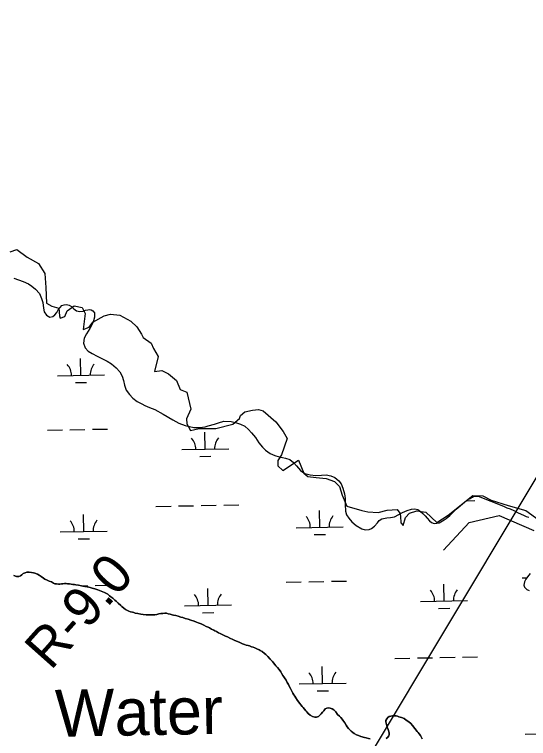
# Model space of a CAD drawing. Extents: x 3925854 to 3964121, y 224593 to 250589.
# Drawn here: x 3947714 to 3948807, y 239589 to 241130 of the extents above; entities that cross this region are included whole.
import ezdxf

# ---------------------------------------------------------------- set-up
doc = ezdxf.new("R2010")
doc.units = 0
for name, color, linetype in [('V-RIVR-EDGE', 7, 'Continuous'), ('V-RIVR-IDEN', 7, 'Continuous'), ('V-RIVR-RANG-IDEN', 7, 'Continuous'), ('V-RRAP-FSHR', 7, 'Continuous'), ('V-TOPO-SHOR', 7, 'Continuous'), ('V-UTIL-LINE', 7, 'Continuous'), ('V-WETL-SWMP', 7, 'Continuous')]:
    doc.layers.add(name, color=color, linetype=linetype)

msp = doc.modelspace()

# ---------------------------------------------------------------- linework, layer by layer
at = {"layer": 'V-RIVR-EDGE'}
msp.add_lwpolyline([(3947704.798, 240625.245), (3947719.549, 240630.163), (3947740.858, 240613.772), (3947765.444, 240600.659), (3947778.557, 240579.351), (3947781.015, 240549.028), (3947782.654, 240516.246), (3947793.309, 240509.689), (3947808.88, 240505.592), (3947809.699, 240489.201), (3947811.339, 240484.284), (3947821.173, 240487.562), (3947826.09, 240499.855), (3947840.842, 240510.509), (3947858.053, 240506.411), (3947864.609, 240494.118), (3947860.511, 240459.697), (3947872.805, 240464.614), (3947881, 240475.269), (3947904.767, 240489.201), (3947918.699, 240492.479), (3947938.368, 240490.02), (3947961.315, 240477.727), (3947974.428, 240465.434), (3947984.263, 240449.863), (3947987.541, 240442.487), (3948004.751, 240431.013), (3948009.669, 240419.539), (3948019.503, 240402.329), (3948012.127, 240370.367), (3948027.699, 240372.825), (3948041.631, 240365.449), (3948058.841, 240351.517), (3948066.217, 240331.848), (3948080.969, 240326.111), (3948089.165, 240290.051), (3948080.15, 240269.563), (3948080.969, 240258.908), (3948088.345, 240244.976), (3948107.195, 240249.074), (3948142.435, 240249.074), (3948178.495, 240258.089), (3948192.427, 240270.382), (3948194.886, 240276.938), (3948203.901, 240284.314), (3948220.292, 240288.412), (3948233.405, 240289.232), (3948243.239, 240286.773), (3948270.284, 240263.006), (3948285.856, 240242.518), (3948294.051, 240227.766), (3948281.758, 240193.345), (3948274.382, 240181.052), (3948274.382, 240169.578), (3948285.036, 240159.743), (3948317.818, 240181.871), (3948329.292, 240154.007), (3948338.307, 240146.631), (3948355.517, 240144.992), (3948376.825, 240142.533), (3948394.855, 240135.977), (3948405.509, 240125.323), (3948411.246, 240107.293), (3948421.081, 240083.526), (3948453.043, 240074.511), (3948465.336, 240072.052), (3948487.464, 240070.413), (3948506.313, 240075.33), (3948527.622, 240076.969), (3948533.358, 240068.774), (3948534.998, 240062.217), (3948535.817, 240048.285), (3948540.734, 240042.548), (3948545.652, 240059.759), (3948553.847, 240068.774), (3948569.418, 240073.691), (3948589.088, 240071.232), (3948612.035, 240049.105), (3948636.621, 240064.676), (3948689.072, 240106.473), (3948710.38, 240105.653), (3948727.591, 240096.638), (3948763.651, 240085.165), (3948801.35, 240074.511), (3948830.034, 240054.022)], dxfattribs=at)
at = {"layer": 'V-RRAP-FSHR'}
msp.add_lwpolyline([(3948626.157, 239990.445), (3948680.818, 240048.86), (3948744.685, 240063.583), (3948818.268, 240032.187)], dxfattribs=at)
at = {"layer": 'V-TOPO-SHOR'}
for points in [[(3947712.714, 239935.894), (3947718.647, 239934.219), (3947723.284, 239933.969), (3947726.829, 239935.243), (3947729.574, 239937.334), (3947733.035, 239940.322), (3947736.987, 239942.198), (3947740.731, 239943.269), (3947745.474, 239943.521), (3947750.41, 239942.866), (3947754.635, 239941.815), (3947757.654, 239941.076), (3947763.38, 239938.899), (3947766.585, 239936.746), (3947770.992, 239933.877), (3947775.598, 239930.502), (3947778.807, 239928.653), (3947784.028, 239926.379), (3947788.042, 239924.421), (3947793.168, 239922.654), (3947797.272, 239919.586), (3947800.289, 239918.746), (3947803.613, 239918.208), (3947807.641, 239917.661), (3947810.871, 239917.931), (3947814.002, 239918.302), (3947817.132, 239918.572), (3947820.564, 239918.838), (3947823.892, 239918.904), (3947827.32, 239918.669), (3947831.148, 239918.324), (3947835.076, 239917.78), (3947838.498, 239917.038), (3947841.622, 239916.704), (3947844.745, 239916.268), (3947850.684, 239915.297), (3947856.525, 239914.228), (3947859.847, 239913.69), (3947864.176, 239912.84), (3947869.008, 239911.881), (3947872.026, 239911.142), (3947875.045, 239910.507), (3947879.37, 239909.352), (3947885.406, 239907.777), (3947891.335, 239905.699), (3947895.154, 239904.347), (3947902.185, 239901.551), (3947905.296, 239900.107), (3947909.611, 239897.945), (3947912.519, 239896.2), (3947916.521, 239893.132), (3947919.323, 239890.883), (3947923.226, 239887.918), (3947927.523, 239884.041), (3947930.318, 239881.288), (3947934.713, 239877.106), (3947940.311, 239872.308), (3947942.711, 239870.266), (3947946.61, 239866.897), (3947950.209, 239863.833), (3947953.016, 239862.291), (3947957.235, 239860.534), (3947961.155, 239859.18), (3947964.977, 239858.031), (3947968.194, 239857.091), (3947971.111, 239856.254), (3947976.847, 239854.984), (3947982.784, 239853.712), (3947988.021, 239852.952), (3947994.47, 239852.381), (3948000.524, 239852.418), (3948006.271, 239852.258), (3948012.429, 239852.698), (3948017.074, 239853.356), (3948021.321, 239854.32)], [(3948021.321, 239854.32), (3948025.462, 239854.984), (3948029.706, 239855.645), (3948033.642, 239855.908), (3948037.271, 239855.668), (3948040.691, 239854.826), (3948044.918, 239853.974), (3948049.547, 239852.817), (3948052.566, 239852.08), (3948057.495, 239850.818), (3948062.12, 239849.46), (3948067.852, 239847.785), (3948071.975, 239846.534), (3948077.103, 239844.967), (3948083.64, 239843.185), (3948089.37, 239841.309), (3948096.102, 239838.919), (3948101.128, 239837.154), (3948104.945, 239835.702), (3948110.971, 239833.117), (3948116.793, 239830.435), (3948122.013, 239827.958), (3948126.13, 239826.101), (3948129.04, 239824.659), (3948133.351, 239822.294), (3948137.767, 239820.029), (3948140.574, 239818.486), (3948143.581, 239816.641), (3948148.197, 239814.274), (3948151.308, 239812.728), (3948155.521, 239810.567), (3948160.039, 239808.502), (3948162.949, 239807.059), (3948166.965, 239805.304), (3948171.882, 239802.832), (3948178.507, 239799.735), (3948181.62, 239798.494), (3948186.644, 239796.626), (3948191.867, 239794.453), (3948194.779, 239793.212), (3948198.789, 239790.75), (3948203.614, 239789.188), (3948206.831, 239788.248), (3948211.054, 239786.992), (3948213.971, 239786.155), (3948218.091, 239784.701), (3948221.608, 239783.353), (3948225.425, 239782.001), (3948229.644, 239780.242), (3948234.164, 239778.28), (3948236.871, 239776.84), (3948240.982, 239774.377), (3948245.883, 239770.391), (3948248.58, 239767.841), (3948252.973, 239763.561), (3948257.861, 239758.365), (3948262.748, 239752.969), (3948264.74, 239750.528), (3948267.827, 239746.763), (3948270.02, 239744.22), (3948273.61, 239740.249), (3948276.695, 239736.181), (3948280.471, 239730.797), (3948282.257, 239727.955), (3948285.036, 239723.588), (3948286.822, 239720.746), (3948289.802, 239716.277), (3948291.788, 239713.23), (3948294.365, 239708.765), (3948296.835, 239703.899), (3948298.416, 239700.655), (3948300.783, 239695.586), (3948302.962, 239691.629), (3948306.229, 239685.745), (3948308.31, 239682.194), (3948310.196, 239679.149), (3948312.578, 239675.493), (3948316.352, 239669.906), (3948321.132, 239663.905), (3948323.02, 239661.161), (3948325.906, 239657.501), (3948327.901, 239655.161), (3948330.788, 239651.701), (3948333.983, 239648.441), (3948335.974, 239646), (3948338.964, 239642.539), (3948343.062, 239638.764), (3948347.676, 239636.296), (3948352.501, 239634.734), (3948356.436, 239634.793), (3948360.384, 239636.266), (3948363.333, 239638.656), (3948366.289, 239641.55), (3948369.35, 239644.947), (3948372.009, 239648.449), (3948374.972, 239652.05), (3948378.318, 239653.831), (3948381.956, 239654.296), (3948385.476, 239653.555), (3948389.499, 239652.304), (3948393.111, 239650.45)], [(3948393.111, 239650.45), (3948397.703, 239645.863), (3948401.275, 239640.077), (3948405.274, 239636.808), (3948408.068, 239633.853), (3948410.859, 239630.697), (3948412.649, 239628.158), (3948414.437, 239625.518), (3948416.319, 239622.27), (3948419.297, 239617.598), (3948421.578, 239613.842), (3948424.165, 239610.287), (3948426.958, 239607.534), (3948429.959, 239604.98), (3948433.457, 239601.919), (3948436.16, 239599.875), (3948441.778, 239596.891), (3948445.595, 239595.439), (3948450.92, 239593.569), (3948458.666, 239591.369), (3948462.188, 239590.626), (3948466.915, 239589.366), (3948470.737, 239588.32)], [(3948504.735, 239588.975), (3948507.682, 239591.062), (3948510.441, 239594.564), (3948511.18, 239597.683), (3948510.916, 239601.519), (3948508.77, 239608.401), (3948506.806, 239613.564), (3948505.151, 239619.331), (3948503.892, 239624.387), (3948504.025, 239627.513), (3948505.677, 239631.125), (3948508.127, 239633.824), (3948511.07, 239635.711), (3948514.105, 239636.587), (3948517.945, 239637.253), (3948521.277, 239637.724), (3948525.51, 239637.275), (3948528.629, 239636.536), (3948531.746, 239635.696), (3948537.274, 239633.824), (3948542.498, 239631.754), (3948547.307, 239628.575), (3948552.614, 239624.789), (3948556.707, 239620.814), (3948560.699, 239616.636), (3948570.658, 239604.327), (3948572.651, 239601.988), (3948574.84, 239599.039), (3948577.523, 239595.279), (3948579.7, 239591.222), (3948581.085, 239588.385)]]:
    msp.add_lwpolyline(points, dxfattribs=at)
at = {"layer": 'V-UTIL-LINE'}
msp.add_lwpolyline([(3951084.343, 243921.319), (3947981.77, 238738.296), (3948844.302, 237642.921), (3949260.796, 236134.673), (3945931.135, 235655.081), (3945509.058, 234777.685), (3942603.575, 230254.808)], dxfattribs=at)
at = {"layer": 'V-WETL-SWMP'}
for p, q in [((3947855.392, 240362.345), (3947854.738, 240398.339)), ((3947805.401, 240361.436), (3947905.384, 240363.254)), ((3947843.675, 240346.699), (3947867.671, 240347.135)), ((3947784.095, 240245.598), (3947816.09, 240246.179)), ((3947832.087, 240246.47), (3947864.082, 240247.052)), ((3947880.079, 240247.343), (3947912.074, 240247.925)), ((3948119.728, 240205.263), (3948119.073, 240241.257)), ((3948069.736, 240204.354), (3948169.72, 240206.172)), ((3948108.01, 240189.616), (3948132.006, 240190.053)), ((3948674.753, 240095.264), (3948692.88, 240095.594)), ((3948015.084, 240083.269), (3948047.079, 240083.851)), ((3948063.076, 240084.142), (3948095.071, 240084.724)), ((3948111.068, 240085.015), (3948143.063, 240085.596)), ((3948159.061, 240085.887), (3948191.055, 240086.469)), ((3947861.44, 240029.725), (3947860.786, 240065.719)), ((3948363.265, 240038.85), (3948362.611, 240074.844)), ((3947811.449, 240028.816), (3947911.432, 240030.634)), ((3948313.274, 240037.941), (3948413.257, 240039.759)), ((3947849.723, 240014.079), (3947873.719, 240014.515)), ((3948351.548, 240023.203), (3948375.544, 240023.64)), ((3948291.968, 239922.102), (3948323.963, 239922.684)), ((3948339.96, 239922.975), (3948371.955, 239923.557)), ((3948387.952, 239923.848), (3948419.947, 239924.429)), ((3948793.793, 239931.227), (3948803.644, 239931.406)), ((3947856.77, 239914.189), (3947870.13, 239914.432)), ((3947886.127, 239914.723), (3947918.122, 239915.305)), ((3948125.776, 239872.643), (3948125.121, 239908.637)), ((3948627.601, 239881.768), (3948626.946, 239917.762)), ((3948577.609, 239880.859), (3948677.593, 239882.677)), ((3948075.784, 239871.734), (3948175.768, 239873.552)), ((3948615.883, 239866.121), (3948639.879, 239866.557)), ((3948114.058, 239856.996), (3948138.054, 239857.433)), ((3948522.957, 239759.774), (3948554.952, 239760.356)), ((3948570.95, 239760.647), (3948602.944, 239761.228)), ((3948618.942, 239761.519), (3948650.936, 239762.101)), ((3948666.934, 239762.392), (3948698.928, 239762.974)), ((3948369.313, 239706.23), (3948368.659, 239742.224)), ((3948319.322, 239705.321), (3948419.305, 239707.139)), ((3948357.596, 239690.583), (3948381.592, 239691.02)), ((3948799.841, 239598.607), (3948831.836, 239599.189))]:
    msp.add_line(p, q, dxfattribs=at)
for points in [[(3947713.091, 240569.298), (3947722.635, 240565.568), (3947732.883, 240561.73), (3947743.928, 240556.875), (3947750.938, 240552.062), (3947758.641, 240545.93), (3947767.318, 240536.459), (3947771.851, 240526.124), (3947774.179, 240517.224), (3947775.773, 240505.608), (3947777.306, 240497.725), (3947781.971, 240490.515), (3947789.695, 240486.4), (3947795.863, 240487.849), (3947800.335, 240491.131), (3947804.218, 240495.933), (3947807.406, 240501.85), (3947811.09, 240506.956), (3947814.759, 240510.65), (3947819.721, 240512.515), (3947824.769, 240512.967), (3947830.203, 240511.7), (3947835.317, 240508.823), (3947840.614, 240504.128), (3947846.218, 240499.834), (3947852.956, 240497.949), (3947859.926, 240498.885), (3947865.392, 240500.745), (3947869.942, 240501.908), (3947874.384, 240502.265), (3947877.404, 240501.629), (3947881.015, 240499.776), (3947884.399, 240495.403), (3947884.204, 240486.328), (3947882.509, 240478.478), (3947879.712, 240471.345), (3947874.673, 240462.017), (3947867.598, 240450.895), (3947862.654, 240441.061), (3947860.733, 240430.894)], [(3947860.733, 240430.894), (3947864.761, 240420.564), (3947871.047, 240413.943), (3947879.161, 240408.513), (3947889.996, 240402.853), (3947900.132, 240397.906), (3947911.268, 240392.142), (3947920.39, 240386.702), (3947930.793, 240378.323), (3947938.066, 240369.674), (3947942.915, 240360.647), (3947946.042, 240350.931), (3947948.16, 240341.226), (3947951.784, 240330.8), (3947958.543, 240321.147), (3947965.927, 240313.506), (3947975.434, 240306.246), (3947984.664, 240301.41), (3947991.386, 240298.011), (3948001.228, 240293.875), (3948012.378, 240289.422), (3948030.232, 240279.856), (3948051.182, 240267.233), (3948064.019, 240260.14), (3948077.182, 240255.263), (3948095.7, 240251.339), (3948108.507, 240251.004), (3948119.519, 240252.806), (3948126.294, 240254.451), (3948139.346, 240258.35), (3948147.744, 240260.885), (3948159.279, 240264.397), (3948175.313, 240264.028), (3948185.977, 240261.396), (3948194.823, 240258.48), (3948203.955, 240253.947), (3948212.152, 240246.802), (3948218.436, 240240.08), (3948226.599, 240229.606), (3948233.851, 240218.94), (3948241.319, 240209.583), (3948248.005, 240202.655), (3948257.618, 240195.898), (3948267.562, 240191.962), (3948277.115, 240189.14), (3948284.257, 240187.25), (3948290.395, 240185.774), (3948299.745, 240182.853), (3948307.346, 240176.621), (3948313.727, 240169.495), (3948317.814, 240164.813), (3948322.7, 240159.416), (3948331.714, 240153.271), (3948342.677, 240150.232), (3948354.772, 240149.4), (3948366.782, 240150.083), (3948376.672, 240150.585), (3948386.537, 240148.667), (3948395.073, 240145.049), (3948403.671, 240137.697), (3948408.648, 240131.291), (3948412.383, 240121.872), (3948415.79, 240110.035), (3948417.605, 240100.233), (3948417.57, 240087.121), (3948417.831, 240073.401), (3948420.367, 240065.103), (3948424.933, 240057.995), (3948431.616, 240050.765), (3948440.912, 240042.599), (3948452.54, 240035.62), (3948459.781, 240033.628), (3948468.061, 240034.45), (3948473.426, 240036.311), (3948479.731, 240041.289), (3948485.757, 240048.488), (3948489.841, 240053.288), (3948495.426, 240056.861), (3948506.042, 240059.272), (3948514.012, 240059.492), (3948522.096, 240060.921), (3948531.729, 240065.764), (3948539.341, 240070.324), (3948548.865, 240074.462), (3948558.072, 240077.191), (3948565.14, 240077.924), (3948571.983, 240076.441), (3948577.794, 240072.649), (3948582.187, 240068.266), (3948587.376, 240062.867), (3948591.563, 240058.183), (3948596.449, 240052.686), (3948601.148, 240048.704), (3948606.478, 240047.135), (3948612.33, 240047.377), (3948616.983, 240048.64), (3948621.039, 240050.716), (3948628.144, 240054.98), (3948632.104, 240057.561), (3948639.838, 240064.138), (3948653.593, 240077.41)], [(3948653.593, 240077.41), (3948675.551, 240095.937), (3948678.357, 240097.765), (3948682.87, 240100.446), (3948685.797, 240102.03), (3948688.359, 240103.249), (3948690.432, 240104.223), (3948692.627, 240104.832), (3948695.432, 240105.197), (3948699.944, 240104.829), (3948753.836, 240083.71), (3948761.273, 240080.293), (3948768.102, 240077.973), (3948775.905, 240074.799), (3948784.074, 240070.528), (3948791.389, 240066.5), (3948796.388, 240064.547), (3948802.484, 240062.106), (3948807.605, 240060.274)], [(3948021.321, 239854.321), (3948017.074, 239853.356), (3948012.428, 239852.698), (3948006.271, 239852.258), (3948000.523, 239852.418), (3947994.471, 239852.38), (3947988.021, 239852.952), (3947982.784, 239853.712), (3947976.846, 239854.984), (3947971.11, 239856.254), (3947968.194, 239857.091), (3947964.976, 239858.032), (3947961.155, 239859.181), (3947957.235, 239860.533), (3947953.017, 239862.292), (3947950.209, 239863.834), (3947946.61, 239866.897), (3947942.711, 239870.266), (3947940.311, 239872.308), (3947934.713, 239877.107), (3947930.318, 239881.288), (3947927.522, 239884.04), (3947923.226, 239887.918), (3947919.323, 239890.883), (3947916.522, 239893.131), (3947912.519, 239896.199), (3947909.612, 239897.944), (3947905.297, 239900.107), (3947902.185, 239901.551), (3947895.154, 239904.347), (3947891.335, 239905.698), (3947885.406, 239907.777), (3947879.37, 239909.352), (3947875.045, 239910.507), (3947872.026, 239911.143), (3947869.007, 239911.881), (3947864.176, 239912.839), (3947859.847, 239913.69), (3947856.524, 239914.229), (3947850.685, 239915.298), (3947844.744, 239916.268), (3947841.622, 239916.704), (3947838.499, 239917.039), (3947835.077, 239917.78), (3947831.149, 239918.325), (3947827.32, 239918.668), (3947823.893, 239918.905), (3947820.564, 239918.839), (3947817.131, 239918.572), (3947814.002, 239918.301), (3947810.871, 239917.931), (3947807.641, 239917.661), (3947803.612, 239918.208), (3947800.289, 239918.746), (3947797.272, 239919.585), (3947793.168, 239922.653), (3947788.042, 239924.421), (3947784.028, 239926.379), (3947778.807, 239928.652), (3947775.598, 239930.501), (3947770.993, 239933.877), (3947766.585, 239936.747), (3947763.38, 239938.899), (3947757.653, 239941.076), (3947754.635, 239941.814), (3947750.409, 239942.866), (3947745.474, 239943.522), (3947740.731, 239943.269), (3947736.988, 239942.198), (3947733.034, 239940.323), (3947729.574, 239937.333), (3947726.829, 239935.243), (3947723.285, 239933.969), (3947718.648, 239934.219), (3947712.715, 239935.894)], [(3948810.361, 239940.767), (3948804.992, 239933.452), (3948801.698, 239928.454), (3948798.769, 239922.845), (3948796.937, 239915.407), (3948798.398, 239911.626), (3948803.762, 239906.502), (3948808.883, 239904.427)], [(3948393.111, 239650.45), (3948389.499, 239652.303), (3948385.477, 239653.555), (3948381.955, 239654.297), (3948378.319, 239653.831), (3948374.972, 239652.05), (3948372.009, 239648.45), (3948369.35, 239644.947), (3948366.289, 239641.549), (3948363.334, 239638.655), (3948360.384, 239636.265), (3948356.435, 239634.793), (3948352.501, 239634.733), (3948347.676, 239636.296), (3948343.062, 239638.764), (3948338.965, 239642.539), (3948335.975, 239645.999), (3948333.983, 239648.441), (3948330.789, 239651.701), (3948327.9, 239655.161), (3948325.907, 239657.501), (3948323.02, 239661.162), (3948321.132, 239663.905), (3948316.353, 239669.906), (3948312.578, 239675.493), (3948310.195, 239679.148), (3948308.31, 239682.194), (3948306.229, 239685.746), (3948302.962, 239691.63), (3948300.784, 239695.586), (3948298.415, 239700.654), (3948296.835, 239703.898), (3948294.364, 239708.765), (3948291.788, 239713.23), (3948289.802, 239716.276), (3948286.823, 239720.745), (3948285.037, 239723.588), (3948282.258, 239727.954), (3948280.472, 239730.797), (3948276.695, 239736.182), (3948273.61, 239740.248), (3948270.02, 239744.219), (3948267.827, 239746.764), (3948264.74, 239750.528), (3948262.748, 239752.969), (3948257.861, 239758.366), (3948252.973, 239763.561), (3948248.579, 239767.842), (3948245.882, 239770.392), (3948240.981, 239774.377), (3948236.871, 239776.84), (3948234.163, 239778.28), (3948229.644, 239780.243), (3948225.426, 239782.002), (3948221.608, 239783.353), (3948218.091, 239784.7), (3948213.971, 239786.155), (3948211.055, 239786.992), (3948206.831, 239788.247), (3948203.613, 239789.188), (3948198.788, 239790.751), (3948194.779, 239793.213), (3948191.867, 239794.454), (3948186.644, 239796.626), (3948181.621, 239798.494), (3948178.507, 239799.736), (3948171.882, 239802.831), (3948166.965, 239805.303), (3948162.949, 239807.059), (3948160.039, 239808.502), (3948155.521, 239810.566), (3948151.307, 239812.728), (3948148.196, 239814.273), (3948143.581, 239816.641), (3948140.574, 239818.487), (3948137.766, 239820.029), (3948133.352, 239822.294), (3948129.039, 239824.659), (3948126.129, 239826.101), (3948122.013, 239827.959), (3948116.793, 239830.434), (3948110.971, 239833.117), (3948104.946, 239835.701), (3948101.128, 239837.153), (3948096.103, 239838.92), (3948089.37, 239841.31), (3948083.64, 239843.185), (3948077.103, 239844.967), (3948071.975, 239846.533), (3948067.852, 239847.786), (3948062.12, 239849.46), (3948057.495, 239850.819), (3948052.566, 239852.08), (3948049.547, 239852.818), (3948044.919, 239853.975), (3948040.692, 239854.826), (3948037.271, 239855.668), (3948033.643, 239855.908), (3948029.706, 239855.646), (3948025.463, 239854.984), (3948021.321, 239854.321)], [(3948470.737, 239588.319), (3948466.915, 239589.367), (3948462.188, 239590.627), (3948458.665, 239591.369), (3948450.921, 239593.568), (3948445.595, 239595.438), (3948441.777, 239596.89), (3948436.16, 239599.874), (3948433.457, 239601.919), (3948429.959, 239604.981), (3948426.959, 239607.534), (3948424.164, 239610.286), (3948421.578, 239613.843), (3948419.297, 239617.599), (3948416.32, 239622.27), (3948414.437, 239625.517), (3948412.649, 239628.158), (3948410.86, 239630.698), (3948408.068, 239633.854), (3948405.275, 239636.808), (3948401.274, 239640.077), (3948397.703, 239645.863), (3948393.111, 239650.45)], [(3948581.084, 239588.385), (3948579.701, 239591.223), (3948577.524, 239595.28), (3948574.84, 239599.04), (3948572.651, 239601.988), (3948570.658, 239604.328), (3948560.699, 239616.636), (3948556.708, 239620.813), (3948552.614, 239624.789), (3948547.307, 239628.576), (3948542.499, 239631.753), (3948537.275, 239633.825), (3948531.747, 239635.697), (3948528.629, 239636.537), (3948525.51, 239637.275), (3948521.278, 239637.723), (3948517.945, 239637.253), (3948514.105, 239636.587), (3948511.07, 239635.71), (3948508.126, 239633.824), (3948505.677, 239631.126), (3948504.025, 239627.512), (3948503.892, 239624.387), (3948505.151, 239619.331), (3948506.806, 239613.564), (3948508.77, 239608.4), (3948510.917, 239601.519), (3948511.18, 239597.683), (3948510.442, 239594.564), (3948507.682, 239591.062), (3948504.735, 239588.975)]]:
    msp.add_lwpolyline(points, dxfattribs=at)
for centre, start, end in [((3947800.15, 240361.816), 0.269879, 41.813537), ((3947910.618, 240363.824), 140.269876, 181.813534), ((3948064.485, 240204.733), 0.269879, 41.813537), ((3948174.953, 240206.742), 140.269876, 181.813534), ((3948308.023, 240038.32), 0.269879, 41.813537), ((3948418.491, 240040.329), 140.269876, 181.813534), ((3947806.198, 240029.196), 0.269879, 41.813537), ((3947916.666, 240031.204), 140.269876, 181.813534), ((3948070.533, 239872.113), 0.269879, 41.813537), ((3948181.001, 239874.122), 140.269876, 181.813534), ((3948572.358, 239881.238), 0.269879, 41.813537), ((3948682.826, 239883.247), 140.269876, 181.813534), ((3948314.071, 239705.7), 0.269879, 41.813537), ((3948424.539, 239707.709), 140.269876, 181.813534)]:
    msp.add_arc(centre, 35.246, start, end, dxfattribs=at)

# ---------------------------------------------------------------- texts
at = {"layer": 'V-RIVR-IDEN'}
msp.add_text('Water', height=99.9998, rotation=1.067956, dxfattribs=at).set_placement((3947801.508, 239592.718))
at = {"layer": 'V-RIVR-RANG-IDEN'}
msp.add_text('R-9.0', height=83, rotation=48.301202, dxfattribs=at).set_placement((3947791.361, 239732.422))

doc.saveas('drawing.dxf')
